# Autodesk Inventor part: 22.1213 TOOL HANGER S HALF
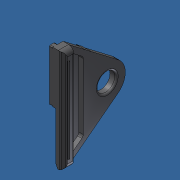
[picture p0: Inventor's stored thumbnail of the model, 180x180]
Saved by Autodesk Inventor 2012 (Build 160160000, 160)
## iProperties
Created: 2017-10
Part Number: 22.1213 TOOL HANGER S HALF
Material: ABS Plastic
Document SubType Name: Modeling
Designer: Admin
Density: 1.06 g/cm^3
Mass: 5.20509 g
Surface Area: 44.7183 cm^2
Volume: 4.91046 cm^3
Translation Standard: STEP AP214IS
FileName: 22_1213_0_2.stp
PreProcessor: ACIS
PostProcessor: Build: 160, Release: 2012 RTM - Date: Tue 03/01/2011
Sent Units: inch
Uncertainty: 0.0
Author: Admin
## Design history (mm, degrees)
feature "Base1"
node "2"
